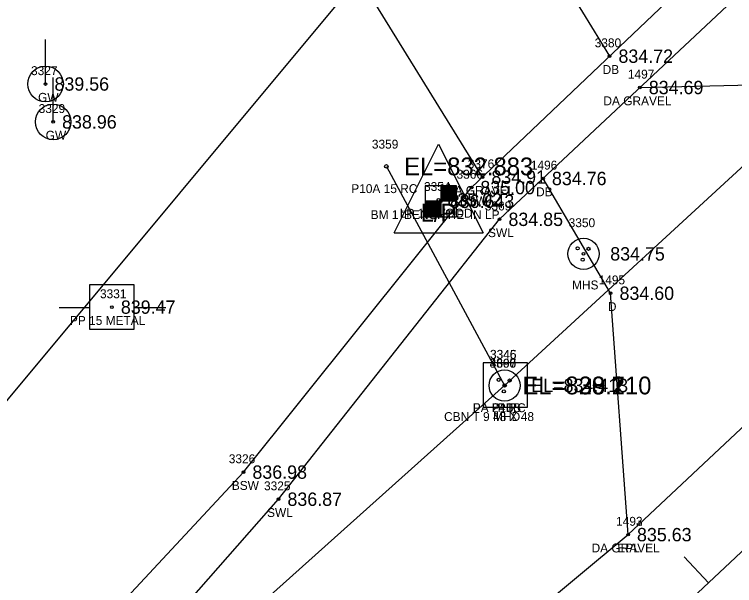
# Model space of a CAD drawing. Extents: x 1622501 to 1626664, y 1117816 to 1121579.
# Drawn here: x 1624202.2 to 1624283.2, y 1119531.1 to 1119595.3 of the extents above; entities that cross this region are included whole.
import ezdxf

# ---------------------------------------------------------------- set-up
doc = ezdxf.new("R2010")
doc.units = 0
for name, color, linetype in [('RD_EX_Conc', 7, 'Continuous'), ('RD_EX_Conc_txCode', 7, 'Continuous'), ('RD_EX_DR_Inlet', 7, 'Continuous'), ('RD_EX_DR_Inlet_txCode', 7, 'Continuous'), ('RD_EX_DR_Pipe', 7, 'Continuous'), ('RD_EX_DR_Pipe_txCode', 7, 'Continuous'), ('RD_EX_Driveway', 7, 'Continuous'), ('RD_EX_Driveway_txCode', 7, 'Continuous'), ('RD_EX_Road', 7, 'Continuous'), ('RD_EX_Road_txCode', 7, 'Continuous'), ('RD_EX_TX_Conc_ELEV', 7, 'Continuous'), ('RD_EX_TX_DR_Inlet_ELEV', 7, 'Continuous'), ('RD_EX_TX_Driveway_ELEV', 7, 'Continuous'), ('RD_EX_TX_Road_ELEV', 7, 'Continuous'), ('RD_EX_TX_UT_ELEV', 7, 'Continuous'), ('RD_EX_UT', 7, 'Continuous'), ('RD_EX_UT_txCode', 7, 'Continuous'), ('RD_EX_VEG', 7, 'Continuous'), ('RD_HC_Cl', 7, 'Continuous'), ('RD_HC_Data_Tic', 7, 'Continuous'), ('RD_HC_Survey', 7, 'Continuous'), ('RD_HC_Survey_ELEV', 7, 'Continuous'), ('RD_HC_Survey_txCode', 7, 'Continuous'), ('RD_SMD_Locator', 7, 'Continuous'), ('RD_TX_Pipe_ElevEX', 7, 'Continuous')]:
    doc.layers.add(name, color=color, linetype=linetype)

msp = doc.modelspace()

# ---------------------------------------------------------------- linework, layer by layer
at = {"layer": 'RD_EX_Conc'}
for points in [[(1623883.581, 1119262.305), (1623914.108, 1119291.006), (1623949.141, 1119315.668), (1623997.41, 1119349.699), (1624041.945, 1119381.589), (1624076.326, 1119409.191), (1624117.505, 1119442.935), (1624154.837, 1119473.105), (1624194.148, 1119507.573), (1624227.988, 1119543.892), (1624253.607, 1119575.877), (1624290.617, 1119611.115), (1624311.927, 1119631.192), (1624320.296, 1119640.908)], [(1623887.302, 1119259.135), (1623917.255, 1119287.494), (1623952.104, 1119311.76), (1624000.174, 1119345.775), (1624044.862, 1119377.79), (1624079.211, 1119405.171), (1624120.295, 1119438.84), (1624157.175, 1119468.813), (1624198.234, 1119502.551), (1624231.925, 1119540.844), (1624256.763, 1119572.31), (1624294.215, 1119607.499), (1624315.431, 1119627.068), (1624326.014, 1119634.835)]]:
    msp.add_lwpolyline(points, dxfattribs=at)
at = {"layer": 'RD_EX_DR_Inlet'}
msp.add_line((1624259.923, 1119551.175), (1624259.923, 1119556.175), dxfattribs=at)
msp.add_lwpolyline([(1624259.923, 1119551.175), (1624259.923, 1119556.175), (1624254.923, 1119556.175), (1624254.923, 1119551.175)], close=True, dxfattribs=at)
for centre, radius in [((1624266.202, 1119568.429), 1.75), ((1624265.538, 1119569.059), 0.175), ((1624266.762, 1119568.989), 0.175), ((1624266.115, 1119567.764), 0.175), ((1624257.332, 1119553.63), 1.75), ((1624256.667, 1119554.26), 0.175), ((1624257.892, 1119554.19), 0.175), ((1624257.244, 1119552.965), 0.175)]:
    msp.add_circle(centre, radius, dxfattribs=at)
at = {"layer": 'RD_EX_DR_Pipe'}
msp.add_line((1624244.044, 1119578.26), (1624257.332, 1119553.63), dxfattribs=at)
msp.add_lwpolyline([(1623859.42, 1119207.437), (1623928.357, 1119275.93), (1624053.588, 1119378.714), (1624148.045, 1119455.705), (1624257.332, 1119553.63), (1624257.332, 1119553.63), (1624370.574, 1119657.838)], dxfattribs=at)
at = {"layer": 'RD_EX_Driveway'}
for p, q in [((1624257.119, 1119610.303), (1624269.126, 1119590.653)), ((1624254.847, 1119577.058), (1624240.491, 1119600.343)), ((1624272.537, 1119587.131), (1624326.188, 1119588.447))]:
    msp.add_line(p, q, dxfattribs=at)
msp.add_lwpolyline([(1624271.208, 1119536.86), (1624269.246, 1119563.997), (1624261.651, 1119576.902)], dxfattribs=at)
at = {"layer": 'RD_EX_Road'}
msp.add_lwpolyline([(1623871.531, 1119282.432), (1623877.354, 1119269.364), (1623882.942, 1119261.681), (1623889.315, 1119256.289), (1623900.771, 1119250.58), (1623911.744, 1119248.838), (1623922.606, 1119250.096), (1623930.438, 1119253.064), (1623938.728, 1119260.806), (1623940.655, 1119261.073), (1623977.454, 1119294.807), (1624012.801, 1119327.203), (1624055.337, 1119364.807), (1624091.922, 1119394.374), (1624132.971, 1119426.419), (1624171.164, 1119456.673), (1624210.906, 1119487.895), (1624248.425, 1119517.93), (1624271.208, 1119536.86), (1624326.188, 1119588.447), (1624377.27, 1119636.651)], dxfattribs=at)
at = {"layer": 'RD_EX_UT'}
for p, q in [((1624205.744, 1119587.523), (1624205.744, 1119592.523)), ((1624206.599, 1119583.262), (1624206.599, 1119588.262)), ((1624244.906, 1119570.774), (1624249.906, 1119580.774)), ((1624249.906, 1119580.774), (1624254.906, 1119570.774)), ((1624244.906, 1119570.774), (1624254.906, 1119570.774)), ((1624215.696, 1119564.949), (1624210.696, 1119564.949)), ((1624210.696, 1119564.949), (1624210.696, 1119559.949)), ((1624215.696, 1119559.949), (1624215.696, 1119564.949)), ((1624207.265, 1119562.387), (1624210.734, 1119562.387)), ((1624215.625, 1119562.387), (1624219.265, 1119562.387)), ((1624210.696, 1119559.949), (1624215.696, 1119559.949))]:
    msp.add_line(p, q, dxfattribs=at)
for centre in [(1624205.744, 1119587.524), (1624206.599, 1119583.262)]:
    msp.add_circle(centre, 1.999, dxfattribs=at)
at = {"layer": 'RD_EX_VEG'}
msp.add_lwpolyline([(1624170.048, 1119570.178), (1624164.903, 1119535.447), (1624182.088, 1119528.79), (1624240.275, 1119598.637), (1624220.351, 1119640.931)], dxfattribs=at)
at = {"layer": 'RD_HC_Cl'}
msp.add_line((1623937.248, 1119209.793), (1624678.651, 1119905.108), dxfattribs=at)
at = {"layer": 'RD_HC_Data_Tic'}
msp.add_line((1624280.232, 1119531.456), (1624277.496, 1119534.374), dxfattribs=at)
at = {"layer": 'RD_HC_Survey'}
for p, q in [((1624250.17, 1119576.084), (1624250.17, 1119572.584)), ((1624250.188, 1119576.084), (1624250.188, 1119574.334)), ((1624250.213, 1119576.084), (1624250.213, 1119574.334)), ((1624250.237, 1119576.084), (1624250.237, 1119574.334)), ((1624250.262, 1119576.084), (1624250.262, 1119574.334)), ((1624250.287, 1119576.084), (1624250.287, 1119574.334)), ((1624250.312, 1119576.084), (1624250.312, 1119574.334)), ((1624250.336, 1119576.084), (1624250.336, 1119574.334)), ((1624250.361, 1119576.084), (1624250.361, 1119574.334)), ((1624250.386, 1119576.084), (1624250.386, 1119574.334)), ((1624250.411, 1119576.084), (1624250.411, 1119574.334)), ((1624250.435, 1119576.084), (1624250.435, 1119574.334)), ((1624250.46, 1119576.084), (1624250.46, 1119574.334)), ((1624250.485, 1119576.084), (1624250.485, 1119574.334)), ((1624250.51, 1119576.084), (1624250.51, 1119574.334)), ((1624250.534, 1119576.084), (1624250.534, 1119574.334)), ((1624250.559, 1119576.084), (1624250.559, 1119574.334)), ((1624250.584, 1119576.084), (1624250.584, 1119574.334)), ((1624250.609, 1119576.084), (1624250.609, 1119574.334)), ((1624250.633, 1119576.084), (1624250.633, 1119574.334)), ((1624250.658, 1119576.084), (1624250.658, 1119574.334)), ((1624250.683, 1119576.084), (1624250.683, 1119574.334)), ((1624250.708, 1119576.084), (1624250.708, 1119574.334)), ((1624250.732, 1119576.084), (1624250.732, 1119574.334)), ((1624250.757, 1119576.084), (1624250.757, 1119574.334)), ((1624250.782, 1119576.084), (1624250.782, 1119574.334)), ((1624250.807, 1119576.084), (1624250.807, 1119574.334)), ((1624250.831, 1119576.084), (1624250.831, 1119574.334)), ((1624250.856, 1119576.084), (1624250.856, 1119574.334)), ((1624250.881, 1119576.084), (1624250.881, 1119574.334)), ((1624250.906, 1119576.084), (1624250.906, 1119574.334)), ((1624250.93, 1119576.084), (1624250.93, 1119574.334)), ((1624250.955, 1119576.084), (1624250.955, 1119574.334)), ((1624250.98, 1119576.084), (1624250.98, 1119574.334)), ((1624251.005, 1119576.084), (1624251.005, 1119574.334)), ((1624251.029, 1119576.084), (1624251.029, 1119574.334)), ((1624251.054, 1119576.084), (1624251.054, 1119574.334)), ((1624251.079, 1119576.084), (1624251.079, 1119574.334)), ((1624251.104, 1119576.084), (1624251.104, 1119574.334)), ((1624251.128, 1119576.084), (1624251.128, 1119574.334)), ((1624251.153, 1119576.084), (1624251.153, 1119574.334)), ((1624251.178, 1119576.084), (1624251.178, 1119574.334)), ((1624251.203, 1119576.084), (1624251.203, 1119574.334)), ((1624251.227, 1119576.084), (1624251.227, 1119574.334)), ((1624251.252, 1119576.084), (1624251.252, 1119574.334)), ((1624251.277, 1119576.084), (1624251.277, 1119574.334)), ((1624251.302, 1119576.084), (1624251.302, 1119574.334)), ((1624251.326, 1119576.084), (1624251.326, 1119574.334)), ((1624251.351, 1119576.084), (1624251.351, 1119574.334)), ((1624251.376, 1119576.084), (1624251.376, 1119574.334)), ((1624251.401, 1119576.084), (1624251.401, 1119574.334)), ((1624251.425, 1119576.084), (1624251.425, 1119574.334)), ((1624251.45, 1119576.084), (1624251.45, 1119574.334)), ((1624251.475, 1119576.084), (1624251.475, 1119574.334)), ((1624251.5, 1119576.084), (1624251.5, 1119574.334)), ((1624251.524, 1119576.084), (1624251.524, 1119574.334)), ((1624251.549, 1119576.084), (1624251.549, 1119574.334)), ((1624251.574, 1119576.084), (1624251.574, 1119574.334)), ((1624251.599, 1119576.084), (1624251.599, 1119574.334)), ((1624251.623, 1119576.084), (1624251.623, 1119574.334)), ((1624251.648, 1119576.084), (1624251.648, 1119574.334)), ((1624251.673, 1119576.084), (1624251.673, 1119574.334)), ((1624251.698, 1119576.084), (1624251.698, 1119574.334)), ((1624251.722, 1119576.084), (1624251.722, 1119574.334)), ((1624251.747, 1119576.084), (1624251.747, 1119574.334)), ((1624251.772, 1119576.084), (1624251.772, 1119574.334)), ((1624251.797, 1119576.084), (1624251.797, 1119574.334)), ((1624251.821, 1119576.084), (1624251.821, 1119574.334)), ((1624251.846, 1119576.084), (1624251.846, 1119574.334)), ((1624251.871, 1119576.084), (1624251.871, 1119574.334)), ((1624251.896, 1119576.084), (1624251.896, 1119574.334)), ((1624251.92, 1119574.334), (1624248.42, 1119574.334)), ((1624248.42, 1119574.334), (1624248.42, 1119572.584)), ((1624248.445, 1119574.334), (1624248.445, 1119572.584)), ((1624248.47, 1119574.334), (1624248.47, 1119572.584)), ((1624248.495, 1119574.334), (1624248.495, 1119572.584)), ((1624248.519, 1119574.334), (1624248.519, 1119572.584)), ((1624248.544, 1119574.334), (1624248.544, 1119572.584)), ((1624248.569, 1119574.334), (1624248.569, 1119572.584)), ((1624248.594, 1119574.334), (1624248.594, 1119572.584)), ((1624248.618, 1119574.334), (1624248.618, 1119572.584)), ((1624248.643, 1119574.334), (1624248.643, 1119572.584)), ((1624248.668, 1119574.334), (1624248.668, 1119572.584)), ((1624248.693, 1119574.334), (1624248.693, 1119572.584)), ((1624248.717, 1119574.334), (1624248.717, 1119572.584)), ((1624248.742, 1119574.334), (1624248.742, 1119572.584)), ((1624248.767, 1119574.334), (1624248.767, 1119572.584)), ((1624248.792, 1119574.334), (1624248.792, 1119572.584)), ((1624248.816, 1119574.334), (1624248.816, 1119572.584)), ((1624248.841, 1119574.334), (1624248.841, 1119572.584)), ((1624248.866, 1119574.334), (1624248.866, 1119572.584)), ((1624248.891, 1119574.334), (1624248.891, 1119572.584)), ((1624248.915, 1119574.334), (1624248.915, 1119572.584)), ((1624248.94, 1119574.334), (1624248.94, 1119572.584)), ((1624248.965, 1119574.334), (1624248.965, 1119572.584)), ((1624248.99, 1119574.334), (1624248.99, 1119572.584)), ((1624249.014, 1119574.334), (1624249.014, 1119572.584)), ((1624249.039, 1119574.334), (1624249.039, 1119572.584)), ((1624249.064, 1119574.334), (1624249.064, 1119572.584)), ((1624249.089, 1119574.334), (1624249.089, 1119572.584)), ((1624249.113, 1119574.334), (1624249.113, 1119572.584)), ((1624249.138, 1119574.334), (1624249.138, 1119572.584)), ((1624249.163, 1119574.334), (1624249.163, 1119572.584)), ((1624249.188, 1119574.334), (1624249.188, 1119572.584)), ((1624249.212, 1119574.334), (1624249.212, 1119572.584)), ((1624249.237, 1119574.334), (1624249.237, 1119572.584)), ((1624249.262, 1119574.334), (1624249.262, 1119572.584)), ((1624249.287, 1119574.334), (1624249.287, 1119572.584)), ((1624249.311, 1119574.334), (1624249.311, 1119572.584)), ((1624249.336, 1119574.334), (1624249.336, 1119572.584)), ((1624249.361, 1119574.334), (1624249.361, 1119572.584)), ((1624249.386, 1119574.334), (1624249.386, 1119572.584)), ((1624249.41, 1119574.334), (1624249.41, 1119572.584)), ((1624249.435, 1119574.334), (1624249.435, 1119572.584)), ((1624249.46, 1119574.334), (1624249.46, 1119572.584)), ((1624249.484, 1119574.334), (1624249.484, 1119572.584)), ((1624249.509, 1119574.334), (1624249.509, 1119572.584)), ((1624249.534, 1119574.334), (1624249.534, 1119572.584)), ((1624249.559, 1119574.334), (1624249.559, 1119572.584)), ((1624249.583, 1119574.334), (1624249.583, 1119572.584)), ((1624249.608, 1119574.334), (1624249.608, 1119572.584)), ((1624249.633, 1119574.334), (1624249.633, 1119572.584)), ((1624249.658, 1119574.334), (1624249.658, 1119572.584)), ((1624249.682, 1119574.334), (1624249.682, 1119572.584)), ((1624249.707, 1119574.334), (1624249.707, 1119572.584)), ((1624249.732, 1119574.334), (1624249.732, 1119572.584)), ((1624249.757, 1119574.334), (1624249.757, 1119572.584)), ((1624249.781, 1119574.334), (1624249.781, 1119572.584)), ((1624249.806, 1119574.334), (1624249.806, 1119572.584)), ((1624249.831, 1119574.334), (1624249.831, 1119572.584)), ((1624249.856, 1119574.334), (1624249.856, 1119572.584)), ((1624249.88, 1119574.334), (1624249.88, 1119572.584)), ((1624249.905, 1119574.334), (1624249.905, 1119572.584)), ((1624249.93, 1119574.334), (1624249.93, 1119572.584)), ((1624249.955, 1119574.334), (1624249.955, 1119572.584)), ((1624249.979, 1119574.334), (1624249.979, 1119572.584)), ((1624250.004, 1119574.334), (1624250.004, 1119572.584)), ((1624250.029, 1119574.334), (1624250.029, 1119572.584)), ((1624250.054, 1119574.334), (1624250.054, 1119572.584)), ((1624250.078, 1119574.334), (1624250.078, 1119572.584)), ((1624250.103, 1119574.334), (1624250.103, 1119572.584)), ((1624250.128, 1119574.334), (1624250.128, 1119572.584)), ((1624250.153, 1119574.334), (1624250.153, 1119572.584))]:
    msp.add_line(p, q, dxfattribs=at)
msp.add_lwpolyline([(1624251.92, 1119576.084), (1624248.42, 1119576.084), (1624248.42, 1119572.584), (1624251.92, 1119572.584)], close=True, dxfattribs=at)
at = {"layer": 'RD_SMD_Locator'}
for centre, radius in [((1624269.126, 1119590.653), 0.15), ((1624205.744, 1119587.523), 0.15), ((1624272.537, 1119587.131), 0.15), ((1624206.599, 1119583.262), 0.15), ((1624244.044, 1119578.26), 0.2), ((1624254.847, 1119577.058), 0.15), ((1624261.651, 1119576.902), 0.15), ((1624253.607, 1119575.877), 0.15), ((1624249.906, 1119574.498), 0.15), ((1624250.17, 1119574.334), 0.15), ((1624256.763, 1119572.31), 0.15), ((1624266.202, 1119568.429), 0.15), ((1624269.246, 1119563.997), 0.15), ((1624213.205, 1119562.44), 0.15), ((1624257.332, 1119553.63), 0.2), ((1624257.332, 1119553.63), 0.2), ((1624257.332, 1119553.63), 0.2), ((1624257.332, 1119553.63), 0.15), ((1624257.332, 1119553.63), 0.15), ((1624227.988, 1119543.892), 0.15), ((1624231.925, 1119540.844), 0.15), ((1624271.208, 1119536.86), 0.15), ((1624271.208, 1119536.86), 0.15)]:
    msp.add_circle(centre, radius, dxfattribs=at)

# ---------------------------------------------------------------- texts
at = {"layer": 'RD_EX_Conc_txCode'}
for s, p in [('3366', (1624251.93, 1119576.877)), ('BSW', (1624252.292, 1119573.877)), ('3369', (1624255.109, 1119573.31)), ('SWL', (1624255.472, 1119570.31)), ('3326', (1624226.335, 1119544.892)), ('BSW', (1624226.673, 1119541.892)), ('3325', (1624230.295, 1119541.844)), ('SWL', (1624230.634, 1119538.844))]:
    msp.add_text(s, height=1, dxfattribs=at).set_placement(p)
at = {"layer": 'RD_EX_DR_Inlet_txCode'}
for s, p in [('3346', (1624255.678, 1119556.63)), ('3345', (1624255.702, 1119556.63)), ('CBN T 9 48 X 48', (1624250.529, 1119549.63)), ('MHD', (1624256.041, 1119549.63))]:
    msp.add_text(s, height=1, dxfattribs=at).set_placement(p)
at = {"layer": 'RD_EX_DR_Pipe_txCode'}
for s, p in [('3359', (1624242.414, 1119580.26)), ('P10A 15 RC', (1624240.099, 1119575.26)), ('4696', (1624255.655, 1119555.63)), ('3360', (1624255.639, 1119555.63)), ('4697', (1624255.678, 1119555.63)), ('PA 24 RC', (1624253.757, 1119550.63)), ('P10B', (1624255.899, 1119550.63)), ('PB', (1624256.552, 1119550.63))]:
    msp.add_text(s, height=1, dxfattribs=at).set_placement(p)
at = {"layer": 'RD_EX_Driveway_txCode'}
for s, p in [('3380', (1624267.457, 1119591.653)), ('DB', (1624268.347, 1119588.653)), ('1497', (1624271.19, 1119588.131)), ('DA GRAVEL', (1624268.434, 1119585.131)), ('3376', (1624253.193, 1119578.058)), ('1496', (1624260.28, 1119577.902)), ('DA GRAVEL', (1624250.744, 1119575.058)), ('DB', (1624260.871, 1119574.902)), ('1495', (1624267.899, 1119564.997)), ('D', (1624268.939, 1119561.997)), ('1493', (1624269.862, 1119537.86)), ('DA GRAVEL', (1624267.106, 1119534.86))]:
    msp.add_text(s, height=1, dxfattribs=at).set_placement(p)
at = {"layer": 'RD_EX_Road_txCode'}
for s, p in [('1492', (1624269.862, 1119537.86)), ('EPL', (1624270.004, 1119534.86))]:
    msp.add_text(s, height=1, dxfattribs=at).set_placement(p)
at = {"layer": 'RD_EX_TX_Conc_ELEV'}
for s, p in [('835.00', (1624254.607, 1119575.127)), ('834.85', (1624257.763, 1119571.56)), ('836.98', (1624228.988, 1119543.142)), ('836.87', (1624232.925, 1119540.094))]:
    msp.add_text(s, height=1.5, dxfattribs=at).set_placement(p)
at = {"layer": 'RD_EX_TX_DR_Inlet_ELEV'}
for s in ['EL=834.413', 'EL=834.41']:
    msp.add_text(s, height=1.5, dxfattribs=at).set_placement((1624260.332, 1119552.88))
at = {"layer": 'RD_EX_TX_Driveway_ELEV'}
for s, p in [('834.72', (1624270.126, 1119589.903)), ('834.69', (1624273.537, 1119586.381)), ('834.91', (1624255.847, 1119576.308)), ('834.76', (1624262.651, 1119576.152)), ('834.60', (1624270.246, 1119563.247)), ('835.63', (1624272.208, 1119536.11))]:
    msp.add_text(s, height=1.5, dxfattribs=at).set_placement(p)
at = {"layer": 'RD_EX_TX_Road_ELEV'}
msp.add_text('835.63', height=1.5, dxfattribs=at).set_placement((1624272.208, 1119536.11))
at = {"layer": 'RD_EX_TX_UT_ELEV'}
for s, p in [('839.56', (1624206.744, 1119586.773)), ('838.96', (1624207.599, 1119582.512)), ('835.02', (1624250.906, 1119573.748)), ('834.75', (1624269.202, 1119567.679))]:
    msp.add_text(s, height=1.5, dxfattribs=at).set_placement(p)
at = {"layer": 'RD_EX_UT'}
msp.add_text('L/P', height=2, dxfattribs=at).set_placement((1624247.897, 1119572.055))
at = {"layer": 'RD_EX_UT_txCode'}
for s, p in [('3327', (1624204.114, 1119588.523)), ('GW', (1624204.902, 1119585.523)), ('3329', (1624204.969, 1119584.262)), ('GW', (1624205.756, 1119581.262)), ('3354', (1624248.276, 1119575.498)), ('LP 10 WOOD', (1624245.551, 1119572.498)), ('3350', (1624264.533, 1119571.429)), ('MHS', (1624264.911, 1119564.429)), ('3331', (1624211.859, 1119563.44)), ('PP 15 METAL', (1624208.481, 1119560.44))]:
    msp.add_text(s, height=1, dxfattribs=at).set_placement(p)
at = {"layer": 'RD_HC_Survey_ELEV'}
for s, p in [('836.643', (1624251.17, 1119573.584)), ('839.47', (1624214.205, 1119561.69))]:
    msp.add_text(s, height=1.5, dxfattribs=at).set_placement(p)
at = {"layer": 'RD_HC_Survey_txCode'}
for s, p in [('11', (1624250.005, 1119575.334)), ("BM 1 'BENCHTIE' IN LP", (1624242.281, 1119572.334))]:
    msp.add_text(s, height=1, dxfattribs=at).set_placement(p)
at = {"layer": 'RD_TX_Pipe_ElevEX'}
for s, p in [('EL=832.883', (1624246.044, 1119577.26)), ('EL=830.710', (1624259.332, 1119552.63)), ('EL=829.110', (1624259.332, 1119552.63)), ('EL=828.210', (1624259.332, 1119552.63))]:
    msp.add_text(s, height=2, dxfattribs=at).set_placement(p)

doc.saveas('drawing.dxf')
